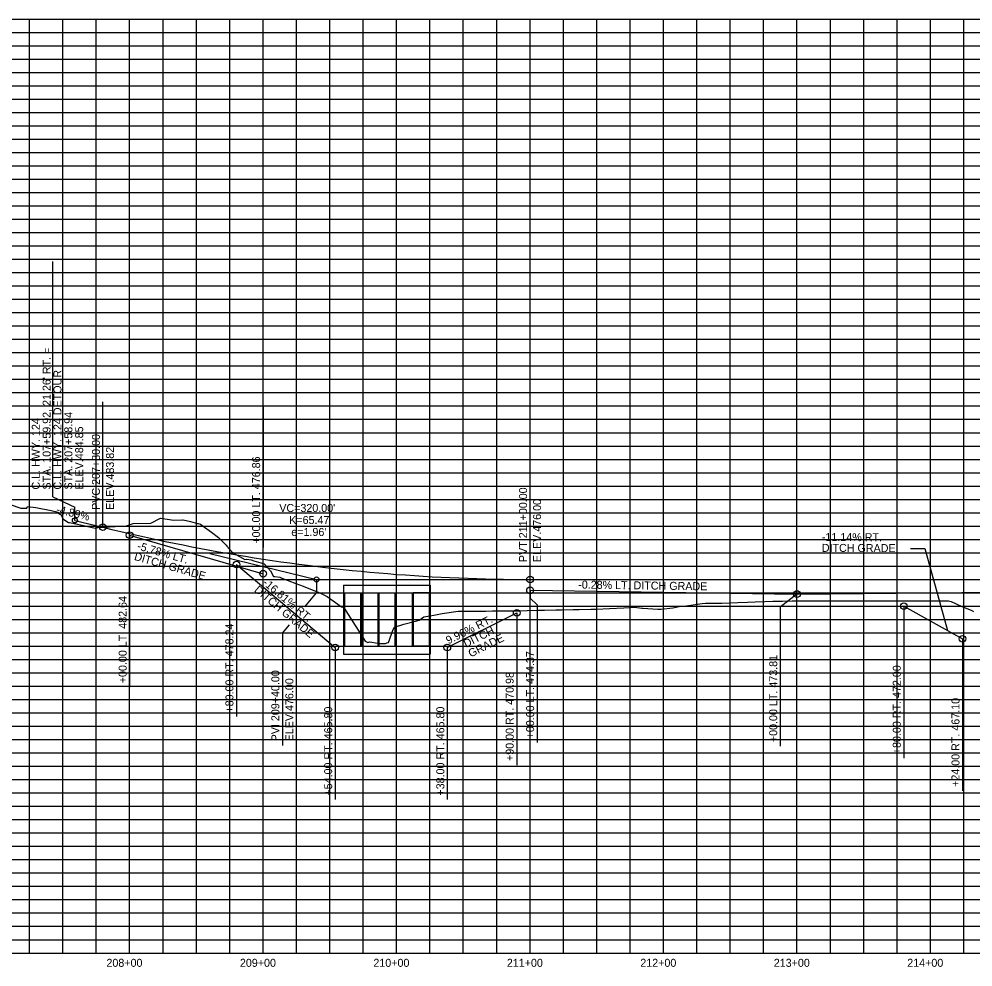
# Model space of a CAD drawing. Extents: x 1054002 to 1056762, y 395173 to 397393.
# Drawn here: x 1054749 to 1055464, y 395173 to 395883 of the extents above; entities that cross this region are included whole.
import ezdxf

# ---------------------------------------------------------------- set-up
doc = ezdxf.new("R2010")
doc.units = 0
for name, color, linetype in [('R_Axis_Annotation', 7, 'Continuous'), ('R_Drainage', 7, 'Continuous'), ('R_Exist Surface', 7, 'Continuous'), ('R_Grid', 7, 'Continuous'), ('R_Grid_Minor', 7, 'Continuous'), ('R_Vert Alg', 7, 'Continuous'), ('R_Vert Alg Annot', 7, 'Continuous')]:
    doc.layers.add(name, color=color, linetype=linetype)

msp = doc.modelspace()

# ---------------------------------------------------------------- linework, layer by layer
at = {"layer": 'R_Drainage'}
for p, q in [((1054992.5, 395459.15), (1054992.5, 395407.48)), ((1054992.5, 395459.15), (1055057.49, 395459.15)), ((1055057.49, 395459.15), (1055057.49, 395407.48)), ((1054993.18, 395453.31), (1054993.18, 395413.31)), ((1054993.18, 395453.31), (1055005.36, 395453.31)), ((1055005.36, 395453.31), (1055005.36, 395413.31)), ((1055006.04, 395453.31), (1055006.04, 395413.31)), ((1055006.04, 395453.31), (1055018.22, 395453.31)), ((1055018.22, 395453.31), (1055018.22, 395413.31)), ((1055018.9, 395453.31), (1055018.9, 395413.31)), ((1055018.9, 395453.31), (1055031.08, 395453.31)), ((1055031.08, 395453.31), (1055031.08, 395413.31)), ((1055031.76, 395453.31), (1055031.76, 395413.31)), ((1055031.76, 395453.31), (1055043.95, 395453.31)), ((1055043.95, 395453.31), (1055043.95, 395413.31)), ((1055044.62, 395453.31), (1055044.62, 395413.31)), ((1055056.81, 395453.31), (1055044.62, 395453.31)), ((1055056.81, 395453.31), (1055056.81, 395413.31)), ((1054992.5, 395407.48), (1055057.49, 395407.48)), ((1054993.18, 395413.31), (1055005.36, 395413.31)), ((1055006.04, 395413.31), (1055018.22, 395413.31)), ((1055018.9, 395413.31), (1055031.08, 395413.31)), ((1055031.76, 395413.31), (1055043.95, 395413.31)), ((1055056.81, 395413.31), (1055044.62, 395413.31))]:
    msp.add_line(p, q, dxfattribs=at)
at = {"layer": 'R_Exist Surface'}
msp.add_lwpolyline([(1054742.71, 395519.64), (1054750.85, 395516.73), (1054750.89, 395516.74), (1054751.72, 395516.76), (1054755.31, 395516.9), (1054755.66, 395518.19), (1054761.92, 395517.25), (1054773.38, 395515.09), (1054778.73, 395513.75), (1054778.76, 395513.69), (1054778.94, 395512.85), (1054780.98, 395511.93), (1054782.15, 395508.78), (1054786.58, 395506.17), (1054786.77, 395506.2), (1054787.24, 395506.18), (1054796.69, 395504.19), (1054806.34, 395501.87), (1054808, 395502.26), (1054808.34, 395502.28), (1054808.68, 395502.29), (1054830.04, 395503.66), (1054834.81, 395505.41), (1054848.04, 395505.54), (1054855.47, 395509.35), (1054865.3, 395507.83), (1054871.92, 395508.09), (1054872.49, 395507.97), (1054877.76, 395506.76), (1054883.04, 395505.44), (1054883.58, 395505.29), (1054885.25, 395504.92), (1054888.31, 395502.71), (1054893.59, 395498.8), (1054898.86, 395494.8), (1054898.91, 395494.76), (1054902.45, 395491.36), (1054904.14, 395489.55), (1054904.57, 395489.09), (1054905.07, 395488.24), (1054909.41, 395483.69), (1054909.6, 395483.5), (1054910.1, 395483.21), (1054914.69, 395480.56), (1054918.55, 395478.32), (1054919.94, 395478.67), (1054919.96, 395478.66), (1054923.4, 395477.98), (1054925.24, 395477.45), (1054930.52, 395475.94), (1054933.18, 395475.18), (1054935.79, 395472.08), (1054937.72, 395469.79), (1054940.1, 395465.72), (1054941.07, 395465.57), (1054944.89, 395465.01), (1054946.34, 395464.44), (1054950.27, 395462.9), (1054951.62, 395462.37), (1054956.89, 395460.32), (1054962.17, 395458.28), (1054975.3, 395453.21), (1054980.19, 395450.63), (1054991.09, 395442.97), (1054992.65, 395442.49), (1054994.24, 395440), (1055008.83, 395417.22), (1055010.79, 395416.17), (1055012.12, 395416.76), (1055017.96, 395415.7), (1055018.58, 395415.5), (1055024.07, 395415.46), (1055025.04, 395415.86), (1055026.32, 395416.17), (1055029.6, 395425.94), (1055030.6, 395427.75), (1055037.67, 395429.87), (1055047.54, 395432.37), (1055049.17, 395432.79), (1055052.8, 395435.49), (1055060.07, 395436.73), (1055066.43, 395437.89), (1055078.39, 395439.55), (1055083.46, 395439.66), (1055099.24, 395439.69), (1055104.19, 395439.8), (1055109.53, 395439.92), (1055124.91, 395439.95), (1055130.12, 395440.07), (1055138.31, 395440.26), (1055143.11, 395440.35), (1055151.48, 395440.55), (1055156.08, 395440.63), (1055164.64, 395440.83), (1055169.06, 395440.92), (1055177.79, 395441.12), (1055182.03, 395441.13), (1055191.75, 395441.58), (1055202.58, 395442.24), (1055210.56, 395442.64), (1055215.91, 395441.89), (1055216.68, 395441.97), (1055228.14, 395441.08), (1055230.41, 395441.13), (1055239.37, 395442.22), (1055245.14, 395443.42), (1055247.55, 395443.45), (1055261.27, 395445.37), (1055263.66, 395445.57), (1055275.97, 395445.53), (1055281.95, 395445.81), (1055287.87, 395446.08), (1055295.1, 395446.29), (1055301.02, 395446.56), (1055308.26, 395446.76), (1055314.17, 395447.03), (1055321.41, 395447.24), (1055328.6, 395447.45), (1055334.86, 395447.35), (1055342.27, 395447.44), (1055348.47, 395447.35), (1055355.94, 395447.44), (1055362.08, 395447.35), (1055369.6, 395447.44), (1055375.68, 395447.35), (1055383.25, 395447.44), (1055395.93, 395447.45), (1055401.09, 395447.43), (1055406.36, 395447.42), (1055422.02, 395447.34), (1055424.43, 395447.34), (1055426.92, 395447.33), (1055435.26, 395447.28), (1055445.92, 395447.43), (1055447.84, 395446.99), (1055455.78, 395443.22), (1055462.67, 395440.34), (1055464.66, 395439.48)], dxfattribs=at)
at = {"layer": 'R_Grid'}
for p, q in [((1054032.29, 395883.41), (1056732.29, 395883.41)), ((1054032.29, 395883.41), (1056732.29, 395883.41)), ((1054832.29, 395183.41), (1054832.29, 395883.41)), ((1054932.29, 395183.41), (1054932.29, 395883.41)), ((1055032.29, 395183.41), (1055032.29, 395883.41)), ((1055132.29, 395183.41), (1055132.29, 395883.41)), ((1055232.29, 395183.41), (1055232.29, 395883.41)), ((1055332.29, 395183.41), (1055332.29, 395883.41)), ((1055432.29, 395183.41), (1055432.29, 395883.41)), ((1054032.29, 395833.41), (1056732.29, 395833.41)), ((1054032.29, 395783.41), (1056732.29, 395783.41)), ((1054032.29, 395733.41), (1056732.29, 395733.41)), ((1054032.29, 395683.41), (1056732.29, 395683.41)), ((1054032.29, 395633.41), (1056732.29, 395633.41)), ((1054032.29, 395583.41), (1056732.29, 395583.41)), ((1054032.29, 395533.41), (1056732.29, 395533.41)), ((1054032.29, 395483.41), (1056732.29, 395483.41)), ((1054032.29, 395433.41), (1056732.29, 395433.41)), ((1054032.29, 395383.41), (1056732.29, 395383.41)), ((1054032.29, 395333.41), (1056732.29, 395333.41)), ((1054032.29, 395283.41), (1056732.29, 395283.41)), ((1054032.29, 395233.41), (1056732.29, 395233.41)), ((1054032.29, 395183.41), (1056732.29, 395183.41))]:
    msp.add_line(p, q, dxfattribs=at)
at = {"layer": 'R_Grid_Minor'}
for p, q in [((1054757.29, 395183.41), (1054757.29, 395883.41)), ((1054782.29, 395183.41), (1054782.29, 395883.41)), ((1054807.29, 395183.41), (1054807.29, 395883.41)), ((1054857.29, 395183.41), (1054857.29, 395883.41)), ((1054882.29, 395183.41), (1054882.29, 395883.41)), ((1054907.29, 395183.41), (1054907.29, 395883.41)), ((1054957.29, 395183.41), (1054957.29, 395883.41)), ((1054982.29, 395183.41), (1054982.29, 395883.41)), ((1055007.29, 395183.41), (1055007.29, 395883.41)), ((1055057.29, 395183.41), (1055057.29, 395883.41)), ((1055082.29, 395183.41), (1055082.29, 395883.41)), ((1055107.29, 395183.41), (1055107.29, 395883.41)), ((1055157.29, 395183.41), (1055157.29, 395883.41)), ((1055182.29, 395183.41), (1055182.29, 395883.41)), ((1055207.29, 395183.41), (1055207.29, 395883.41)), ((1055257.29, 395183.41), (1055257.29, 395883.41)), ((1055282.29, 395183.41), (1055282.29, 395883.41)), ((1055307.29, 395183.41), (1055307.29, 395883.41)), ((1055357.29, 395183.41), (1055357.29, 395883.41)), ((1055382.29, 395183.41), (1055382.29, 395883.41)), ((1055407.29, 395183.41), (1055407.29, 395883.41)), ((1055457.29, 395183.41), (1055457.29, 395883.41)), ((1054032.29, 395873.41), (1056732.29, 395873.41)), ((1054032.29, 395863.41), (1056732.29, 395863.41)), ((1054032.29, 395853.41), (1056732.29, 395853.41)), ((1054032.29, 395843.41), (1056732.29, 395843.41)), ((1054032.29, 395823.41), (1056732.29, 395823.41)), ((1054032.29, 395813.41), (1056732.29, 395813.41)), ((1054032.29, 395803.41), (1056732.29, 395803.41)), ((1054032.29, 395793.41), (1056732.29, 395793.41)), ((1054032.29, 395773.41), (1056732.29, 395773.41)), ((1054032.29, 395763.41), (1056732.29, 395763.41)), ((1054032.29, 395753.41), (1056732.29, 395753.41)), ((1054032.29, 395743.41), (1056732.29, 395743.41)), ((1054032.29, 395723.41), (1056732.29, 395723.41)), ((1054032.29, 395713.41), (1056732.29, 395713.41)), ((1054032.29, 395703.41), (1056732.29, 395703.41)), ((1054032.29, 395693.41), (1056732.29, 395693.41)), ((1054032.29, 395673.41), (1056732.29, 395673.41)), ((1054032.29, 395663.41), (1056732.29, 395663.41)), ((1054032.29, 395653.41), (1056732.29, 395653.41)), ((1054032.29, 395643.41), (1056732.29, 395643.41)), ((1054032.29, 395623.41), (1056732.29, 395623.41)), ((1054032.29, 395613.41), (1056732.29, 395613.41)), ((1054032.29, 395603.41), (1056732.29, 395603.41)), ((1054032.29, 395593.41), (1056732.29, 395593.41)), ((1054032.29, 395573.41), (1056732.29, 395573.41)), ((1054032.29, 395563.41), (1056732.29, 395563.41)), ((1054032.29, 395553.41), (1056732.29, 395553.41)), ((1054032.29, 395543.41), (1056732.29, 395543.41)), ((1054032.29, 395523.41), (1056732.29, 395523.41)), ((1054032.29, 395513.41), (1056732.29, 395513.41)), ((1054032.29, 395503.41), (1056732.29, 395503.41)), ((1054032.29, 395493.41), (1056732.29, 395493.41)), ((1054032.29, 395473.41), (1056732.29, 395473.41)), ((1054032.29, 395463.41), (1056732.29, 395463.41)), ((1054032.29, 395453.41), (1056732.29, 395453.41)), ((1054032.29, 395443.41), (1056732.29, 395443.41)), ((1054032.29, 395423.41), (1056732.29, 395423.41)), ((1054032.29, 395413.41), (1056732.29, 395413.41)), ((1054032.29, 395403.41), (1056732.29, 395403.41)), ((1054032.29, 395393.41), (1056732.29, 395393.41)), ((1054032.29, 395373.41), (1056732.29, 395373.41)), ((1054032.29, 395363.41), (1056732.29, 395363.41)), ((1054032.29, 395353.41), (1056732.29, 395353.41)), ((1054032.29, 395343.41), (1056732.29, 395343.41)), ((1054032.29, 395323.41), (1056732.29, 395323.41)), ((1054032.29, 395313.41), (1056732.29, 395313.41)), ((1054032.29, 395303.41), (1056732.29, 395303.41)), ((1054032.29, 395293.41), (1056732.29, 395293.41)), ((1054032.29, 395273.41), (1056732.29, 395273.41)), ((1054032.29, 395263.41), (1056732.29, 395263.41)), ((1054032.29, 395253.41), (1056732.29, 395253.41)), ((1054032.29, 395243.41), (1056732.29, 395243.41)), ((1054032.29, 395223.41), (1056732.29, 395223.41)), ((1054032.29, 395213.41), (1056732.29, 395213.41)), ((1054032.29, 395203.41), (1056732.29, 395203.41)), ((1054032.29, 395193.41), (1056732.29, 395193.41))]:
    msp.add_line(p, q, dxfattribs=at)
at = {"layer": 'R_Vert Alg'}
for p, q in [((1054791.23, 395507.66), (1054812.29, 395502.52)), ((1054832.29, 395496.61), (1054932.29, 395467.71)), ((1054912.29, 395474.61), (1054986.29, 395412.41)), ((1055132.29, 395463.41), (1055772.29, 395463.41)), ((1055132.29, 395455.26), (1055332.29, 395452.46)), ((1055332.29, 395452.46), (1055579.29, 395454.93)), ((1055412.29, 395443.41), (1055456.29, 395418.91)), ((1055070.29, 395412.41), (1055122.29, 395438.31))]:
    msp.add_line(p, q, dxfattribs=at)
msp.add_lwpolyline([(1054812.29, 395502.52), (1054818.96, 395500.9), (1054825.63, 395499.33), (1054832.29, 395497.78), (1054838.96, 395496.27), (1054845.63, 395494.79), (1054852.29, 395493.35), (1054858.96, 395491.94), (1054865.63, 395490.57), (1054872.29, 395489.23), (1054878.96, 395487.92), (1054885.63, 395486.65), (1054892.29, 395485.41), (1054898.96, 395484.2), (1054905.63, 395483.03), (1054912.29, 395481.9), (1054918.96, 395480.79), (1054925.63, 395479.72), (1054932.29, 395478.69), (1054938.96, 395477.69), (1054945.63, 395476.72), (1054952.29, 395475.79), (1054958.96, 395474.89), (1054965.63, 395474.02), (1054978.96, 395472.39), (1054985.63, 395471.63), (1054992.29, 395470.9), (1054998.96, 395470.2), (1055005.63, 395469.54), (1055012.29, 395468.91), (1055018.96, 395468.32), (1055025.63, 395467.76), (1055032.29, 395467.23), (1055038.96, 395466.74), (1055045.63, 395466.28), (1055052.29, 395465.86), (1055058.96, 395465.47), (1055065.63, 395465.11), (1055072.29, 395464.79), (1055078.96, 395464.5), (1055085.63, 395464.24), (1055092.29, 395464.02), (1055098.96, 395463.84), (1055105.63, 395463.68), (1055112.29, 395463.57), (1055118.96, 395463.48), (1055125.63, 395463.43), (1055132.29, 395463.41)], dxfattribs=at)
at = {"layer": 'R_Vert Alg Annot'}
for p, q in [((1054774.62, 395525.41), (1054774.62, 395701.81)), ((1054812.29, 395512.52), (1054812.29, 395596.52)), ((1054932.29, 395593.66), (1054932.29, 395487.23)), ((1055132.29, 395473.41), (1055132.29, 395557.41)), ((1054774.62, 395525.41), (1054791.23, 395517.66)), ((1054791.23, 395507.66), (1054791.23, 395517.66)), ((1054812.29, 395502.52), (1054812.29, 395512.52)), ((1054832.29, 395496.61), (1054832.29, 395466.61)), ((1054932.29, 395467.71), (1054932.29, 395487.23)), ((1054892.29, 395482.96), (1054972.29, 395463.41)), ((1054912.29, 395474.61), (1054912.29, 395444.61)), ((1055132.29, 395463.41), (1055132.29, 395473.41)), ((1054832.29, 395466.61), (1054832.29, 395382.61)), ((1054972.29, 395463.41), (1054972.29, 395453.41)), ((1054972.29, 395463.41), (1055052.29, 395463.41)), ((1054963.48, 395442.97), (1054972.29, 395453.41)), ((1055132.29, 395455.26), (1055132.29, 395449.47)), ((1055332.29, 395452.46), (1055319.75, 395442.73)), ((1054912.29, 395444.61), (1054912.29, 395360.61)), ((1055137.57, 395444.41), (1055132.29, 395449.47)), ((1055137.57, 395444.41), (1055137.57, 395341.26)), ((1055319.75, 395442.73), (1055319.75, 395338.46)), ((1055412.29, 395443.41), (1055412.29, 395413.41)), ((1055122.29, 395438.31), (1055122.29, 395408.31)), ((1054946.68, 395423.05), (1054951.96, 395429.32)), ((1054946.68, 395423.05), (1054946.68, 395339.05)), ((1055456.29, 395418.91), (1055456.29, 395388.91)), ((1054986.29, 395412.41), (1054986.29, 395382.41)), ((1055070.29, 395412.41), (1055070.29, 395382.41)), ((1055122.29, 395408.31), (1055122.29, 395324.31)), ((1055412.29, 395413.41), (1055412.29, 395329.41)), ((1055456.29, 395388.91), (1055456.29, 395304.91)), ((1054986.29, 395382.41), (1054986.29, 395298.41)), ((1055070.29, 395382.41), (1055070.29, 395298.41))]:
    msp.add_line(p, q, dxfattribs=at)
msp.add_lwpolyline([(1055417.42, 395486.6), (1055428.07, 395486.57), (1055445.08, 395425.16)], dxfattribs=at)
for centre, radius in [((1054791.23, 395507.66), 1.85), ((1054812.29, 395502.52), 2.5), ((1054832.29, 395496.61), 2.5), ((1054912.29, 395474.61), 2.5), ((1054932.29, 395467.71), 2.5), ((1054972.29, 395463.41), 1.85), ((1055132.29, 395463.41), 2.5), ((1055132.29, 395455.26), 2.5), ((1055332.29, 395452.46), 2.5), ((1055412.29, 395443.41), 2.5), ((1055122.29, 395438.31), 2.5), ((1055456.29, 395418.91), 2.5), ((1054986.29, 395412.41), 2.5), ((1055070.29, 395412.41), 2.5)]:
    msp.add_circle(centre, radius, dxfattribs=at)

# ---------------------------------------------------------------- texts
at = {"layer": 'R_Axis_Annotation'}
for s, p in [('208+00', (1054814.89, 395173.06)), ('209+00', (1054914.89, 395173.06)), ('210+00', (1055014.89, 395173.06)), ('211+00', (1055114.89, 395173.06)), ('212+00', (1055214.89, 395173.06)), ('213+00', (1055314.89, 395173.06)), ('214+00', (1055414.89, 395173.06))]:
    msp.add_text(s, height=6, dxfattribs=at).set_placement(p)
at = {"layer": 'R_Vert Alg Annot'}
for s, rotation, p in [("STA. 107+59.92, 21.26' RT. =", 90, (1054773.08, 395530.79)), ('C.L. HWY. 124 DETOUR', 90, (1054781.2, 395530.79)), ('STA. 207+58.94', 90, (1054789.33, 395530.79)), ('C.L. HWY. 124', 90, (1054764.95, 395530.79)), ('ELEV.484.85', 90, (1054797.46, 395530.79)), ('PVC 207+80.00', 90, (1054810.04, 395515.52)), ('ELEV.483.82', 90, (1054820.54, 395515.52)), ('+00.00 LT. 476.86', 90, (1054930.04, 395490.23)), ('PVT 211+00.00', 90, (1055130.04, 395476.41)), ('ELEV.476.00', 90, (1055140.54, 395476.41)), ('-4.89%', 346.26645, (1054776.86, 395513.35)), ('-11.14% RT.', 359.73823, (1055350.91, 395492.22)), ('-5.78% LT.', 343.88071, (1054837.5, 395485.99)), ('DITCH GRADE', 359.73823, (1055350.87, 395484.1)), ('DITCH GRADE', 343.88071, (1054835.24, 395478.18)), ('DITCH GRADE', 319.95159, (1054925.17, 395454.75)), ('-16.81% RT.', 319.95159, (1054931.46, 395460.09)), ('-0.28% LT. DITCH GRADE', 359.19791, (1055168.34, 395456.59)), ('+00.00 LT. 482.64', 90, (1054830.04, 395385.61)), ('9.96% RT.', 26.47684, (1055071.05, 395414.66)), ('+80.00 RT. 478.24', 90, (1054910.04, 395363.61)), ('DITCH', 26.47684, (1055084.22, 395412.14)), ('GRADE', 26.47684, (1055087.81, 395404.84)), ('+00.00 LT. 474.37', 90, (1055135.32, 395344.26)), ('+00.00 LT. 473.81', 90, (1055317.5, 395341.46)), ('PVI 209+40.00', 90, (1054944.43, 395342.05)), ('+90.00 RT. 470.98', 90, (1055120.04, 395327.31)), ('+80.00 RT. 472.00', 90, (1055410.04, 395332.41)), ('ELEV.476.00', 90, (1054954.93, 395342.05)), ('+24.00 RT. 467.10', 90, (1055454.04, 395307.91)), ('+54.00 RT. 465.80', 90, (1054984.04, 395301.41)), ('+38.00 RT. 465.80', 90, (1055068.04, 395301.41))]:
    msp.add_text(s, height=6, rotation=rotation, dxfattribs=at).set_placement(p)
for s, p in [("VC=320.00'", (1054944.39, 395513.97)), ('K=65.47', (1054951.82, 395504.97)), ("e=1.96'", (1054953.39, 395495.97))]:
    msp.add_text(s, height=6, dxfattribs=at).set_placement(p)

doc.saveas('drawing.dxf')
